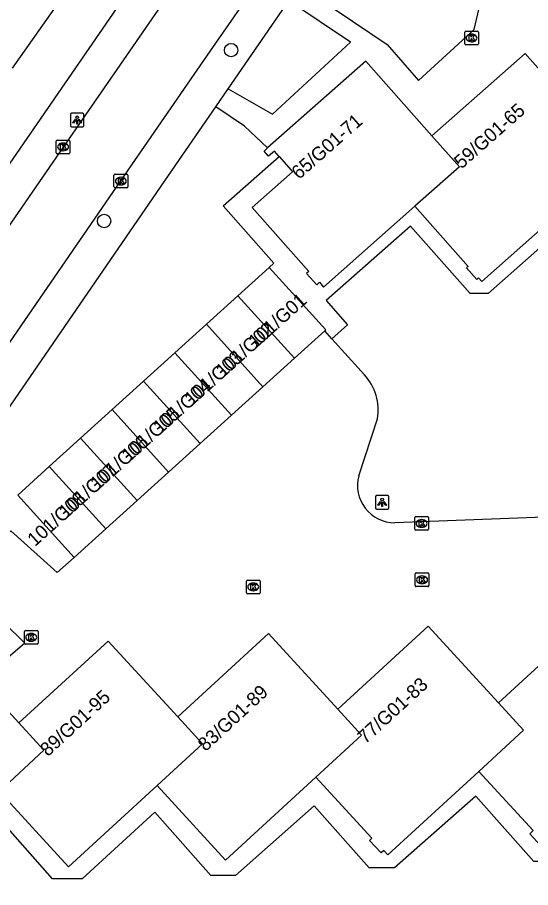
# Model space of a CAD drawing. Extents: x 160356 to 161355, y 381727 to 382845.
# Drawn here: x 160835.4 to 160872.9, y 381947.5 to 382011.2 of the extents above; entities that cross this region are included whole.
import ezdxf

# ---------------------------------------------------------------- set-up
doc = ezdxf.new("R2010")
doc.units = 0
for name, color, linetype in [('IMGEO_Boom', 7, 'Continuous'), ('IMGEO_Kolk', 7, 'Continuous'), ('IMGEO_Lichtpunt', 7, 'Continuous'), ('IMGEO_Pand', 7, 'Continuous'), ('IMGEO_Pand_nummerreeks', 7, 'Continuous'), ('IMGEO_Rijbaan_lokaal_open', 7, 'Continuous'), ('IMGEO_Voetpad_halfverhard', 7, 'Continuous'), ('IMGEO_Voetpad_open', 7, 'Continuous')]:
    doc.layers.add(name, color=color, linetype=linetype)

msp = doc.modelspace()

# ---------------------------------------------------------------- linework, layer by layer
at = {"layer": 'IMGEO_Boom'}
for centre in [(160851.012, 382008.797), (160841.729, 381996.291)]:
    msp.add_circle(centre, 0.489, dxfattribs=at)
at = {"layer": 'IMGEO_Kolk'}
for p, q in [((160868.096, 382009.26), (160868.096, 382010.112)), ((160868.171, 382010.186), (160869.023, 382010.186)), ((160868.584, 382009.966), (160868.609, 382009.966)), ((160869.097, 382010.112), (160869.097, 382009.26)), ((160869.023, 382009.186), (160868.171, 382009.186)), ((160868.607, 382009.406), (160868.582, 382009.406)), ((160838.227, 382001.285), (160838.227, 382002.137)), ((160838.302, 382002.211), (160839.154, 382002.211)), ((160839.228, 382002.137), (160839.228, 382001.285)), ((160838.715, 382001.991), (160838.74, 382001.991)), ((160839.154, 382001.211), (160838.302, 382001.211)), ((160838.738, 382001.431), (160838.713, 382001.431)), ((160842.449, 381998.785), (160842.449, 381999.637)), ((160842.524, 381999.711), (160843.376, 381999.711)), ((160843.45, 381999.637), (160843.45, 381998.785)), ((160842.96, 381998.931), (160842.935, 381998.931)), ((160842.937, 381999.491), (160842.962, 381999.491)), ((160843.376, 381998.711), (160842.524, 381998.711)), ((160864.445, 381973.732), (160864.445, 381974.584)), ((160864.52, 381974.658), (160865.372, 381974.658)), ((160864.933, 381974.438), (160864.958, 381974.438)), ((160865.446, 381974.584), (160865.446, 381973.732)), ((160865.372, 381973.658), (160864.52, 381973.658)), ((160864.956, 381973.878), (160864.931, 381973.878)), ((160864.478, 381969.607), (160864.478, 381970.459)), ((160864.553, 381970.533), (160865.405, 381970.533)), ((160864.966, 381970.313), (160864.991, 381970.313)), ((160865.479, 381970.459), (160865.479, 381969.607)), ((160852.129, 381969.086), (160852.129, 381969.938)), ((160852.204, 381970.012), (160853.056, 381970.012)), ((160852.617, 381969.792), (160852.642, 381969.792)), ((160853.13, 381969.938), (160853.13, 381969.086)), ((160864.989, 381969.753), (160864.964, 381969.753)), ((160853.056, 381969.012), (160852.204, 381969.012)), ((160852.64, 381969.232), (160852.615, 381969.232)), ((160865.405, 381969.533), (160864.553, 381969.533)), ((160835.895, 381965.398), (160835.895, 381966.25)), ((160835.97, 381966.324), (160836.822, 381966.324)), ((160836.383, 381966.104), (160836.408, 381966.104)), ((160836.896, 381966.25), (160836.896, 381965.398)), ((160836.822, 381965.324), (160835.97, 381965.324)), ((160836.406, 381965.544), (160836.381, 381965.544))]:
    msp.add_line(p, q, dxfattribs=at)
for points in [[(160868.096, 382009.26), (160868.096, 382010.112)], [(160868.171, 382010.186), (160869.023, 382010.186)], [(160868.417, 382009.886), (160868.54, 382009.886), (160868.54, 382009.735), (160868.67, 382009.886), (160868.834, 382009.886), (160868.688, 382009.735), (160868.841, 382009.486), (160868.689, 382009.486), (160868.604, 382009.65), (160868.54, 382009.583), (160868.54, 382009.486), (160868.417, 382009.486), (160868.417, 382009.886)], [(160869.097, 382010.112), (160869.097, 382009.26)], [(160869.023, 382009.186), (160868.171, 382009.186)], [(160838.227, 382001.285), (160838.227, 382002.137)], [(160838.302, 382002.211), (160839.154, 382002.211)], [(160839.228, 382002.137), (160839.228, 382001.285)], [(160838.548, 382001.911), (160838.671, 382001.911), (160838.671, 382001.76), (160838.801, 382001.911), (160838.965, 382001.911), (160838.819, 382001.76), (160838.972, 382001.511), (160838.82, 382001.511), (160838.735, 382001.675), (160838.671, 382001.608), (160838.671, 382001.511), (160838.548, 382001.511), (160838.548, 382001.911)], [(160839.154, 382001.211), (160838.302, 382001.211)], [(160842.449, 381998.785), (160842.449, 381999.637)], [(160842.524, 381999.711), (160843.376, 381999.711)], [(160843.45, 381999.637), (160843.45, 381998.785)], [(160842.77, 381999.411), (160842.893, 381999.411), (160842.893, 381999.26), (160843.023, 381999.411), (160843.187, 381999.411), (160843.041, 381999.26), (160843.194, 381999.011), (160843.042, 381999.011), (160842.957, 381999.175), (160842.893, 381999.108), (160842.893, 381999.011), (160842.77, 381999.011), (160842.77, 381999.411)], [(160843.376, 381998.711), (160842.524, 381998.711)], [(160864.445, 381973.732), (160864.445, 381974.584)], [(160864.52, 381974.658), (160865.372, 381974.658)], [(160864.766, 381974.358), (160864.889, 381974.358), (160864.889, 381974.207), (160865.019, 381974.358), (160865.183, 381974.358), (160865.037, 381974.207), (160865.19, 381973.958), (160865.038, 381973.958), (160864.953, 381974.122), (160864.889, 381974.055), (160864.889, 381973.958), (160864.766, 381973.958), (160864.766, 381974.358)], [(160865.446, 381974.584), (160865.446, 381973.732)], [(160865.372, 381973.658), (160864.52, 381973.658)], [(160864.478, 381969.607), (160864.478, 381970.459)], [(160864.553, 381970.533), (160865.405, 381970.533)], [(160865.479, 381970.459), (160865.479, 381969.607)], [(160852.129, 381969.086), (160852.129, 381969.938)], [(160852.204, 381970.012), (160853.056, 381970.012)], [(160852.45, 381969.712), (160852.573, 381969.712), (160852.573, 381969.561), (160852.703, 381969.712), (160852.867, 381969.712), (160852.721, 381969.561), (160852.874, 381969.312), (160852.722, 381969.312), (160852.637, 381969.476), (160852.573, 381969.409), (160852.573, 381969.312), (160852.45, 381969.312), (160852.45, 381969.712)], [(160853.13, 381969.938), (160853.13, 381969.086)], [(160864.799, 381970.233), (160864.922, 381970.233), (160864.922, 381970.082), (160865.052, 381970.233), (160865.216, 381970.233), (160865.07, 381970.082), (160865.223, 381969.833), (160865.071, 381969.833), (160864.986, 381969.997), (160864.922, 381969.93), (160864.922, 381969.833), (160864.799, 381969.833), (160864.799, 381970.233)], [(160853.056, 381969.012), (160852.204, 381969.012)], [(160865.405, 381969.533), (160864.553, 381969.533)], [(160835.895, 381965.398), (160835.895, 381966.25)], [(160835.97, 381966.324), (160836.822, 381966.324)], [(160836.216, 381966.024), (160836.339, 381966.024), (160836.339, 381965.873), (160836.469, 381966.024), (160836.633, 381966.024), (160836.487, 381965.873), (160836.64, 381965.624), (160836.488, 381965.624), (160836.403, 381965.788), (160836.339, 381965.721), (160836.339, 381965.624), (160836.216, 381965.624), (160836.216, 381966.024)], [(160836.896, 381966.25), (160836.896, 381965.398)], [(160836.822, 381965.324), (160835.97, 381965.324)]]:
    msp.add_lwpolyline(points, dxfattribs=at)
for centre, start, end in [((160868.173, 382010.11), 91.55205, 178.44795), ((160868.173, 382010.11), 91.55205, 178.44795), ((160869.021, 382010.11), 1.55205, 88.44795), ((160869.021, 382010.11), 1.55205, 88.44795), ((160868.173, 382009.262), 181.55205, 268.44795), ((160868.173, 382009.262), 181.55205, 268.44795), ((160869.021, 382009.262), 271.55205, 358.44795), ((160869.021, 382009.262), 271.55205, 358.44795), ((160838.304, 382002.135), 91.55205, 178.44795), ((160838.304, 382002.135), 91.55205, 178.44795), ((160839.152, 382002.135), 1.55205, 88.44795), ((160839.152, 382002.135), 1.55205, 88.44795), ((160838.304, 382001.287), 181.55205, 268.44795), ((160838.304, 382001.287), 181.55205, 268.44795), ((160839.152, 382001.287), 271.55205, 358.44795), ((160839.152, 382001.287), 271.55205, 358.44795), ((160842.526, 381999.635), 91.55205, 178.44795), ((160842.526, 381999.635), 91.55205, 178.44795), ((160843.374, 381999.635), 1.55205, 88.44795), ((160843.374, 381999.635), 1.55205, 88.44795), ((160842.526, 381998.787), 181.55205, 268.44795), ((160842.526, 381998.787), 181.55205, 268.44795), ((160843.374, 381998.787), 271.55205, 358.44795), ((160843.374, 381998.787), 271.55205, 358.44795), ((160864.522, 381974.582), 91.55205, 178.44795), ((160864.522, 381974.582), 91.55205, 178.44795), ((160865.37, 381974.582), 1.55205, 88.44795), ((160865.37, 381974.582), 1.55205, 88.44795), ((160864.522, 381973.734), 181.55205, 268.44795), ((160864.522, 381973.734), 181.55205, 268.44795), ((160865.37, 381973.734), 271.55205, 358.44795), ((160865.37, 381973.734), 271.55205, 358.44795), ((160864.555, 381970.457), 91.55205, 178.44795), ((160864.555, 381970.457), 91.55205, 178.44795), ((160865.403, 381970.457), 1.55205, 88.44795), ((160865.403, 381970.457), 1.55205, 88.44795), ((160852.206, 381969.936), 91.55205, 178.44795), ((160852.206, 381969.936), 91.55205, 178.44795), ((160853.054, 381969.936), 1.55205, 88.44795), ((160853.054, 381969.936), 1.55205, 88.44795), ((160852.206, 381969.088), 181.55205, 268.44795), ((160852.206, 381969.088), 181.55205, 268.44795), ((160853.054, 381969.088), 271.55205, 358.44795), ((160853.054, 381969.088), 271.55205, 358.44795), ((160864.555, 381969.609), 181.55205, 268.44795), ((160864.555, 381969.609), 181.55205, 268.44795), ((160865.403, 381969.609), 271.55205, 358.44795), ((160865.403, 381969.609), 271.55205, 358.44795), ((160835.972, 381966.248), 91.55205, 178.44795), ((160835.972, 381966.248), 91.55205, 178.44795), ((160836.82, 381966.248), 1.55205, 88.44795), ((160836.82, 381966.248), 1.55205, 88.44795), ((160835.972, 381965.4), 181.55205, 268.44795), ((160835.972, 381965.4), 181.55205, 268.44795), ((160836.82, 381965.4), 271.55205, 358.44795), ((160836.82, 381965.4), 271.55205, 358.44795)]:
    msp.add_arc(centre, 0.0765, start, end, dxfattribs=at)
for centre, major_axis, ratio, start_param, end_param in [((160868.583, 382009.686), (-0.387, 0.002), 0.722429, 4.712389, 7.853982), ((160868.608, 382009.686), (-0.39, 0.002), 0.717154, 1.570796, 4.712389), ((160838.714, 382001.711), (-0.387, 0.002), 0.722429, 4.712389, 7.853982), ((160838.739, 382001.711), (-0.39, 0.002), 0.717154, 1.570796, 4.712389), ((160842.936, 381999.211), (-0.387, 0.002), 0.722429, 4.712389, 7.853982), ((160842.961, 381999.211), (-0.39, 0.002), 0.717154, 1.570796, 4.712389), ((160864.932, 381974.158), (-0.387, 0.002), 0.722429, 4.712389, 7.853982), ((160864.957, 381974.158), (-0.39, 0.002), 0.717154, 1.570796, 4.712389), ((160864.965, 381970.033), (-0.387, 0.002), 0.722429, 4.712389, 7.853982), ((160864.99, 381970.033), (-0.39, 0.002), 0.717154, 1.570796, 4.712389), ((160852.616, 381969.512), (-0.387, 0.002), 0.722429, 4.712389, 7.853982), ((160852.641, 381969.512), (-0.39, 0.002), 0.717154, 1.570796, 4.712389), ((160836.382, 381965.824), (-0.387, 0.002), 0.722429, 4.712389, 7.853982), ((160836.407, 381965.824), (-0.39, 0.002), 0.717154, 1.570796, 4.712389)]:
    msp.add_ellipse(centre, major_axis=major_axis, ratio=ratio, start_param=start_param, end_param=end_param, dxfattribs=at)
at = {"layer": 'IMGEO_Lichtpunt'}
for p, q in [((160839.257, 382004.083), (160839.257, 382003.276)), ((160839.257, 382004.083), (160839.257, 382003.276)), ((160840.159, 382004.178), (160839.351, 382004.178)), ((160840.159, 382004.178), (160839.351, 382004.178)), ((160840.253, 382003.276), (160840.253, 382004.083)), ((160840.253, 382003.276), (160840.253, 382004.083)), ((160839.351, 382003.182), (160840.159, 382003.182)), ((160839.351, 382003.182), (160840.159, 382003.182)), ((160861.563, 381976.105), (160861.563, 381975.298)), ((160861.563, 381976.105), (160861.563, 381975.298)), ((160862.465, 381976.2), (160861.657, 381976.2)), ((160862.465, 381976.2), (160861.657, 381976.2)), ((160862.559, 381975.298), (160862.559, 381976.105)), ((160862.559, 381975.298), (160862.559, 381976.105)), ((160861.657, 381975.204), (160862.465, 381975.204)), ((160861.657, 381975.204), (160862.465, 381975.204))]:
    msp.add_line(p, q, dxfattribs=at)
for points in [[(160839.631, 382003.747), (160839.67, 382003.719), (160839.482, 382003.457), (160839.444, 382003.484), (160839.631, 382003.747)], [(160839.733, 382003.699), (160839.78, 382003.699), (160839.78, 382003.377), (160839.733, 382003.377), (160839.733, 382003.699)], [(160839.843, 382003.719), (160839.881, 382003.746), (160840.068, 382003.484), (160840.029, 382003.456), (160839.843, 382003.719)], [(160861.937, 381975.769), (160861.976, 381975.741), (160861.788, 381975.479), (160861.75, 381975.506), (160861.937, 381975.769)], [(160862.039, 381975.721), (160862.086, 381975.721), (160862.086, 381975.399), (160862.039, 381975.399), (160862.039, 381975.721)], [(160862.149, 381975.741), (160862.187, 381975.768), (160862.374, 381975.506), (160862.335, 381975.478), (160862.149, 381975.741)]]:
    msp.add_lwpolyline(points, dxfattribs=at)
for centre in [(160839.756, 382003.881), (160862.062, 381975.903)]:
    msp.add_circle(centre, 0.0994, dxfattribs=at)
for centre, start, end in [((160839.351, 382004.083), 90, 180), ((160839.351, 382004.083), 90, 180), ((160840.159, 382004.083), 0, 90), ((160840.159, 382004.083), 0, 90), ((160839.351, 382003.276), 180, 270), ((160839.351, 382003.276), 180, 270), ((160840.159, 382003.276), 270, 0), ((160840.159, 382003.276), 270, 360), ((160861.657, 381976.105), 90, 180), ((160861.657, 381976.105), 90, 180), ((160862.465, 381976.105), 0, 90), ((160862.465, 381976.105), 0, 90), ((160861.657, 381975.298), 180, 270), ((160861.657, 381975.298), 180, 270), ((160862.465, 381975.298), 270, 0), ((160862.465, 381975.298), 270, 360)]:
    msp.add_arc(centre, 0.0946, start, end, dxfattribs=at)
at = {"layer": 'IMGEO_Pand'}
for points in [[(160838.803, 382016.475), (160837.021, 382013.892), (160838.679, 382012.731), (160835.001, 382007.479)], [(160877.378, 382003.052), (160872.511, 382008.553), (160865.703, 382002.529)], [(160865.703, 382002.529), (160860.869, 382007.993), (160853.684, 382001.636)], [(160865.703, 382002.529), (160867.715, 382000.255), (160864.454, 381997.37)], [(160854.518, 382001.011), (160854.176, 382001.397), (160853.757, 382001.026), (160853.423, 382001.405), (160853.684, 382001.636)], [(160854.518, 382001.011), (160855.413, 382000), (160855.511, 381999.889), (160852.549, 381997.268), (160856.688, 381992.591), (160856.539, 381992.46), (160857.273, 381991.63), (160857.47, 381991.804), (160857.775, 381991.459), (160864.454, 381997.37)], [(160864.454, 381997.37), (160868.35, 381992.968), (160868.225, 381992.858), (160868.979, 381992.005), (160869.117, 381992.127), (160869.347, 381991.867), (160876.21, 381997.94)], [(160851.501, 381990.815), (160853.8, 381992.897)], [(160857.858, 381988.257), (160857.937, 381988.328), (160853.8, 381992.897)], [(160849.202, 381988.733), (160851.501, 381990.815)], [(160851.501, 381990.815), (160855.638, 381986.246)], [(160846.902, 381986.651), (160849.202, 381988.733)], [(160853.339, 381984.164), (160849.202, 381988.733)], [(160857.858, 381988.257), (160855.638, 381986.246)], [(160844.603, 381984.568), (160846.902, 381986.651)], [(160851.04, 381982.082), (160846.902, 381986.651)], [(160855.638, 381986.246), (160853.339, 381984.164)], [(160842.304, 381982.486), (160844.603, 381984.568)], [(160844.603, 381984.568), (160848.74, 381980)], [(160853.339, 381984.164), (160851.04, 381982.082)], [(160840.004, 381980.404), (160842.304, 381982.486)], [(160842.304, 381982.486), (160846.441, 381977.918)], [(160851.04, 381982.082), (160848.74, 381980)], [(160837.705, 381978.322), (160840.004, 381980.404)], [(160840.004, 381980.404), (160844.142, 381975.836)], [(160848.74, 381980), (160846.441, 381977.918)], [(160839.544, 381971.672), (160835.406, 381976.24), (160837.705, 381978.322)], [(160841.843, 381973.753), (160837.705, 381978.322)], [(160846.441, 381977.918), (160844.142, 381975.836)], [(160844.142, 381975.836), (160841.843, 381973.753)], [(160841.843, 381973.753), (160839.544, 381971.672)], [(160858.81, 381960.567), (160865.416, 381966.632), (160870.558, 381961.03)], [(160870.558, 381961.03), (160877.078, 381967.015), (160883.942, 381959.538)], [(160847.108, 381960.01), (160853.736, 381966.095), (160858.81, 381960.567)], [(160835.488, 381959.558), (160842.019, 381965.554), (160847.108, 381960.01)], [(160823.707, 381958.976), (160830.39, 381965.111), (160835.488, 381959.558)], [(160869.132, 381956.015), (160872.404, 381959.019), (160870.558, 381961.03)], [(160858.81, 381960.567), (160860.556, 381958.665), (160857.211, 381955.595)], [(160834.045, 381954.546), (160837.325, 381957.557), (160835.488, 381959.558)], [(160847.108, 381960.01), (160848.929, 381958.026), (160845.599, 381954.97)], [(160883.942, 381959.538), (160874.133, 381950.534), (160873.907, 381950.78), (160873.673, 381950.564), (160872.856, 381951.454), (160873.108, 381951.685), (160869.132, 381956.015)], [(160869.132, 381956.015), (160862.476, 381949.905), (160862.179, 381950.228), (160861.983, 381950.049), (160861.142, 381950.965), (160861.315, 381951.124), (160857.211, 381955.595)], [(160857.211, 381955.595), (160850.598, 381949.525), (160845.599, 381954.97)], [(160845.599, 381954.97), (160839.118, 381949.02), (160834.045, 381954.546)]]:
    msp.add_lwpolyline(points, dxfattribs=at)
at = {"layer": 'IMGEO_Rijbaan_lokaal_open'}
for points in [[(160900.454, 382091.336), (160898.732, 382088.827), (160897.579, 382087.17), (160888.911, 382074.534), (160875.487, 382055.069), (160862.667, 382036.458), (160849.849, 382017.829), (160838.733, 382001.705), (160827.599, 381985.555), (160816.487, 381969.406), (160806.996, 381955.65)], [(160811.585, 381953.706), (160812.427, 381954.838), (160843.491, 382000), (160849.506, 382008.744), (160855.258, 382017.034), (160858.854, 382022.23), (160863.124, 382028.242), (160864.448, 382030.182), (160867.631, 382034.676), (160871.484, 382040.355), (160873.174, 382042.828), (160877.127, 382048.557), (160882.027, 382055.784), (160885.092, 382060.107), (160889.498, 382066.61), (160894.202, 382073.493), (160902.442, 382085.568), (160903.558, 382087.228), (160905.012, 382089.324)]]:
    msp.add_lwpolyline(points, dxfattribs=at)
at = {"layer": 'IMGEO_Voetpad_halfverhard'}
for points in [[(160915.299, 382001.716), (160915.08, 382001.395), (160913.919, 381999.699), (160912.273, 381997.514), (160911.323, 381996.603), (160909.897, 381995.445), (160908.243, 381994.267), (160905.471, 381992.456), (160903.516, 381992.456), (160899.275, 381997.25), (160893.335, 381991.995), (160891.46, 381991.995), (160887.454, 381996.521), (160881.709, 381991.436), (160879.901, 381991.436), (160875.697, 381996.188), (160871.918, 381992.844), (160869.823, 381990.99), (160868.489, 381990.99), (160864.123, 381995.923), (160857.956, 381990.466), (160859.518, 381988.701), (160858.381, 381987.677)], [(160853.8, 381992.897), (160854.146, 381993.204), (160850.434, 381997.396), (160854.518, 382001.011)], [(160884.863, 381958.568), (160883.557, 381956.659), (160881.911, 381954.473), (160880.96, 381953.563), (160879.534, 381952.405), (160877.881, 381951.227), (160875.108, 381949.416), (160873.154, 381949.416), (160868.912, 381954.21), (160862.973, 381948.954), (160861.098, 381948.954), (160857.092, 381953.481), (160851.346, 381948.396), (160849.539, 381948.396), (160845.436, 381953.033), (160840.118, 381948.151), (160837.948, 381948.151), (160833.93, 381952.676), (160828.424, 381947.509), (160826.348, 381947.553), (160820.135, 381954.319), (160820.858, 381954.984), (160824.089, 381957.951)]]:
    msp.add_lwpolyline(points, dxfattribs=at)
at = {"layer": 'IMGEO_Voetpad_open'}
for points in [[(160804.86, 381957.022), (160809.509, 381963.746), (160815.556, 381972.499), (160830.024, 381993.552), (160843.658, 382013.325), (160856.447, 382031.904), (160864.216, 382043.168), (160877.531, 382062.485), (160882.102, 382069.151), (160883.88, 382071.73)], [(160856.025, 382013.549), (160862.42, 382009.21), (160864.718, 382006.576), (160868.779, 382010.311), (160869.404, 382012.942), (160868.801, 382014.089)], [(160850.803, 382005.961), (160855.241, 382012.41)], [(160850.803, 382005.961), (160854.038, 382004.118), (160859.749, 382009.38), (160855.241, 382012.41)], [(160849.898, 382004.648), (160850.803, 382005.961)], [(160826.232, 381970.197), (160846.705, 382000), (160849.898, 382004.648)], [(160853.684, 382001.636), (160851.989, 382003.226), (160849.898, 382004.648)], [(160858.381, 381987.677), (160857.858, 381988.257)], [(160860.766, 381985.033), (160858.381, 381987.677)], [(160860.346, 381977.644), (160861.708, 381981.814)], [(160886.731, 381975.114), (160862.985, 381974.206)], [(160839.544, 381971.672), (160838.299, 381970.579), (160834.915, 381973.622), (160830.935, 381969.72), (160832.878, 381968.382), (160835.921, 381965.403), (160834.186, 381963.909), (160830.848, 381967.059), (160826.232, 381970.197)]]:
    msp.add_lwpolyline(points, dxfattribs=at)
for centre, radius, start, end in [((160857.97, 381982.467), 3.795, 350.0849, 42.53801), ((160862.993, 381976.944), 2.738, 165.1885, 269.831)]:
    msp.add_arc(centre, radius, start, end, dxfattribs=at)

# ---------------------------------------------------------------- texts
at = {"layer": 'IMGEO_Pand_nummerreeks'}
for s, rotation, p in [('59/G01-65', 41.50373, (160867.863, 382000.061)), ('65/G01-71', 41.49933, (160855.978, 381999.286)), ('101/G01', 41.93528, (160852.821, 381986.937)), ('101/G02', 41.93528, (160850.438, 381984.796)), ('101/G03', 41.93528, (160848.146, 381982.737)), ('101/G04', 41.93528, (160845.849, 381980.674)), ('101/G05', 41.93528, (160843.552, 381978.61)), ('101/G06', 41.93528, (160841.256, 381976.547)), ('101/G07', 41.93528, (160838.959, 381974.484)), ('101/G08', 41.93528, (160836.664, 381972.422)), ('77/G01-83', 42.55519, (160860.835, 381957.974)), ('89/G01-95', 42.55451, (160837.61, 381957.054)), ('83/G01-89', 42.55426, (160849.142, 381957.425))]:
    msp.add_text(s, height=1, rotation=rotation, dxfattribs=at).set_placement(p)

doc.saveas('drawing.dxf')
